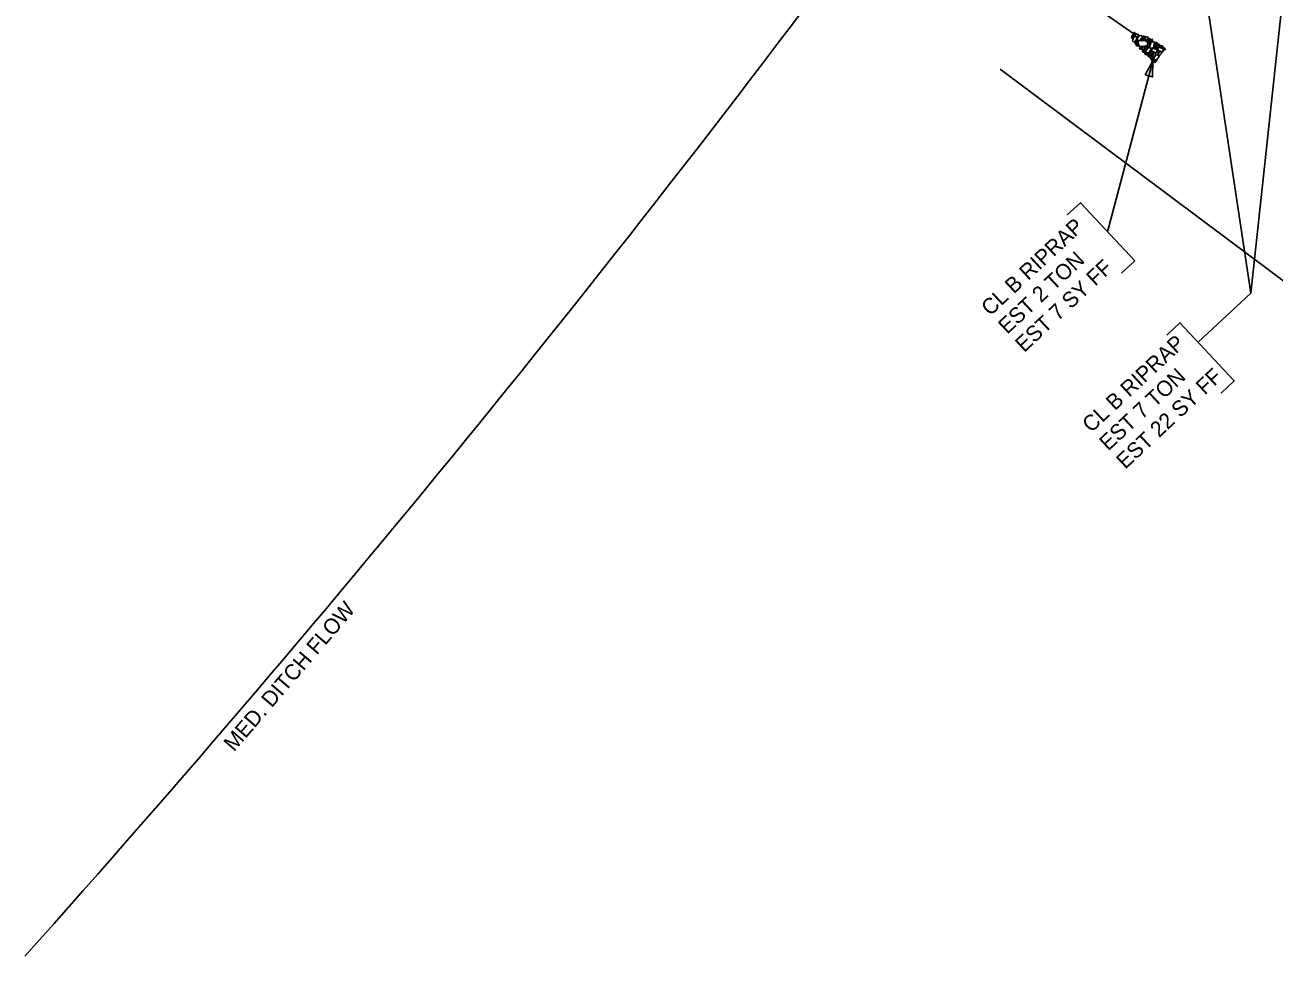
# Model space of a CAD drawing. Extents: x 2384780 to 2405432, y 547869 to 573706.
# Drawn here: x 2399231.9 to 2399632.8, y 560808.7 to 561107.7 of the extents above; entities that cross this region are included whole.
import ezdxf

# ---------------------------------------------------------------- set-up
doc = ezdxf.new("R2010")
doc.units = 0
for name, color, linetype in [('Old_Level_1', 7, 'Continuous'), ('Old_Level_19', 7, 'Continuous'), ('Old_Level_20', 7, 'Continuous'), ('Old_Level_41', 7, 'Continuous'), ('Old_Level_5', 7, 'Continuous')]:
    doc.layers.add(name, color=color, linetype=linetype)

msp = doc.modelspace()

# ---------------------------------------------------------------- linework, layer by layer
at = {"layer": 'Old_Level_1'}
msp.add_line((2399588.2, 561104.64), (2399559.77, 561124.39), dxfattribs=at)
at = {"layer": 'Old_Level_19'}
msp.add_arc((2395689.31, 563976), 4752, 318.20137, 323.62463, dxfattribs=at)
at = {"layer": 'Old_Level_20'}
msp.add_line((2399593.9, 561096.19), (2399579.38, 561041.29), dxfattribs=at)
for points in [[(2399587.72, 561104.23), (2399587.66, 561104.01), (2399587.58, 561103.47), (2399587.23, 561103.47), (2399587.08, 561103.58), (2399587.18, 561104.24), (2399587.48, 561104.4), (2399587.72, 561104.23)], [(2399587.42, 561102.46), (2399587.5, 561102.89), (2399587.79, 561103.88), (2399588.48, 561104.05), (2399588.9, 561103.71), (2399588.48, 561102.56), (2399587.92, 561102.25), (2399587.52, 561102.38)], [(2399588.18, 561105.14), (2399588.12, 561104.91), (2399588.02, 561104.34), (2399587.69, 561104.39), (2399587.52, 561104.49), (2399587.64, 561105.09), (2399587.93, 561105.3), (2399588.18, 561105.14)], [(2399589.32, 561103.96), (2399588.97, 561103.98), (2399588.35, 561104.12), (2399588.2, 561104.64), (2399588.42, 561104.98), (2399589.27, 561104.64), (2399589.41, 561104.31), (2399589.32, 561103.96)], [(2399589.1, 561101.53), (2399588.83, 561101.44), (2399588.36, 561101.62), (2399588.3, 561101.93), (2399588.41, 561102.09), (2399589.02, 561101.93), (2399589.15, 561101.72), (2399589.1, 561101.53)], [(2399588.36, 561102.23), (2399588.48, 561102.42), (2399588.72, 561102.8), (2399589.04, 561102.73), (2399589.2, 561102.62), (2399588.86, 561102.12), (2399588.52, 561102), (2399588.36, 561102.23)], [(2399588.85, 561102.98), (2399589.03, 561103.45), (2399589.59, 561104.3), (2399590.35, 561104.21), (2399590.58, 561103.82), (2399589.83, 561102.83), (2399589.26, 561102.73), (2399588.85, 561102.98)], [(2399592.25, 561101.18), (2399591.45, 561100.87), (2399589.71, 561100.8), (2399589.09, 561101.84), (2399589.34, 561102.63), (2399591.49, 561102.77), (2399592.24, 561102.13), (2399592.41, 561101.2)], [(2399590.83, 561102.73), (2399590.56, 561102.65), (2399590.09, 561102.84), (2399590.01, 561103.14), (2399590.15, 561103.27), (2399590.73, 561103.12), (2399590.84, 561102.95), (2399590.83, 561102.73)], [(2399591.34, 561103.03), (2399591.03, 561102.98), (2399590.59, 561103.19), (2399590.5, 561103.47), (2399590.63, 561103.65), (2399591.27, 561103.45), (2399591.36, 561103.25), (2399591.34, 561103.03)], [(2399591.56, 561103.58), (2399591.28, 561103.49), (2399590.81, 561103.67), (2399590.74, 561103.98), (2399590.88, 561104.12), (2399591.45, 561103.96), (2399591.57, 561103.8), (2399591.56, 561103.58)], [(2399591.38, 561103.04), (2399591.5, 561103.44), (2399591.83, 561103.94), (2399592.39, 561103.84), (2399592.56, 561103.54), (2399592.01, 561102.87), (2399591.61, 561102.87), (2399591.38, 561103.04)], [(2399593.09, 561101.98), (2399592.82, 561101.92), (2399592.38, 561102.12), (2399592.3, 561102.41), (2399592.42, 561102.6), (2399593.02, 561102.4), (2399593.11, 561102.2), (2399593.09, 561101.98)], [(2399593.28, 561102.78), (2399593, 561102.7), (2399592.53, 561102.89), (2399592.46, 561103.18), (2399592.6, 561103.31), (2399593.17, 561103.17), (2399593.29, 561103), (2399593.28, 561102.78)], [(2399594.44, 561102.11), (2399594.4, 561101.57), (2399594.17, 561100.41), (2399593.23, 561100.27), (2399592.82, 561100.54), (2399593.26, 561101.96), (2399593.89, 561102.38), (2399594.5, 561102.22)], [(2399593.8, 561103.04), (2399593.85, 561102.78), (2399593.71, 561102.37), (2399593.39, 561102.23), (2399593.11, 561102.41), (2399593.38, 561102.95), (2399593.64, 561103.14), (2399593.8, 561103.04)], [(2399595.4, 561101.62), (2399595.12, 561101.53), (2399594.66, 561101.71), (2399594.58, 561102.01), (2399594.71, 561102.15), (2399595.29, 561102.01), (2399595.4, 561101.85), (2399595.4, 561101.62)], [(2399589.46, 561100.9), (2399589.16, 561100.86), (2399588.69, 561101.04), (2399588.61, 561101.32), (2399588.74, 561101.51), (2399589.37, 561101.31), (2399589.47, 561101.12), (2399589.46, 561100.9)], [(2399589.64, 561100.06), (2399589.74, 561100.36), (2399589.97, 561100.79), (2399590.31, 561100.68), (2399590.49, 561100.48), (2399590.08, 561100), (2399589.78, 561099.93), (2399589.64, 561100.06)], [(2399590.42, 561099.67), (2399590.4, 561100.03), (2399590.61, 561100.71), (2399591.05, 561100.82), (2399591.29, 561100.64), (2399591.09, 561099.79), (2399590.72, 561099.58), (2399590.42, 561099.67)], [(2399591.45, 561098.95), (2399591.18, 561098.86), (2399590.71, 561099.04), (2399590.65, 561099.35), (2399590.76, 561099.51), (2399591.38, 561099.37), (2399591.5, 561099.15), (2399591.45, 561098.95)], [(2399591.77, 561100.13), (2399591.74, 561099.89), (2399591.64, 561099.37), (2399591.26, 561099.39), (2399591.12, 561099.48), (2399591.27, 561100.11), (2399591.46, 561100.21), (2399591.77, 561100.13)], [(2399592.18, 561100.28), (2399591.92, 561100.19), (2399591.46, 561100.4), (2399591.38, 561100.68), (2399591.5, 561100.86), (2399592.11, 561100.7), (2399592.23, 561100.48), (2399592.18, 561100.28)], [(2399592.19, 561098.21), (2399591.91, 561098.12), (2399591.44, 561098.3), (2399591.39, 561098.61), (2399591.49, 561098.77), (2399592.11, 561098.63), (2399592.23, 561098.41), (2399592.19, 561098.21)], [(2399591.57, 561099.07), (2399591.77, 561099.56), (2399592.41, 561100.35), (2399593.08, 561100.26), (2399593.42, 561099.83), (2399592.67, 561098.89), (2399591.97, 561098.73), (2399591.57, 561099.07)], [(2399592.2, 561100.88), (2399592.27, 561101.2), (2399592.59, 561101.48), (2399592.98, 561101.45), (2399593.07, 561101.25), (2399592.74, 561100.75), (2399592.36, 561100.77), (2399592.2, 561100.88)], [(2399592.94, 561098.77), (2399592.88, 561098.55), (2399592.69, 561098.08), (2399592.39, 561098.02), (2399592.26, 561098.1), (2399592.34, 561098.63), (2399592.61, 561098.81), (2399592.83, 561098.8)], [(2399593.31, 561097.42), (2399592.98, 561097.41), (2399592.5, 561097.56), (2399592.47, 561097.86), (2399592.57, 561098), (2399593.21, 561097.86), (2399593.33, 561097.64), (2399593.31, 561097.42)], [(2399593.74, 561097.99), (2399593.55, 561098.04), (2399593.02, 561098.14), (2399593, 561098.53), (2399593.11, 561098.68), (2399593.77, 561098.51), (2399593.78, 561098.24), (2399593.74, 561097.99)], [(2399593.88, 561098.75), (2399593.57, 561098.68), (2399593.1, 561098.87), (2399593.04, 561099.18), (2399593.17, 561099.32), (2399593.75, 561099.16), (2399593.89, 561098.97), (2399593.88, 561098.75)], [(2399593.73, 561100.21), (2399594.17, 561100.14), (2399595.18, 561099.82), (2399595.31, 561099.15), (2399595.02, 561098.72), (2399593.88, 561099.16), (2399593.46, 561099.62), (2399593.7, 561100.1)], [(2399594.85, 561098.65), (2399594.82, 561098.27), (2399594.52, 561097.6), (2399594.1, 561097.53), (2399593.86, 561097.7), (2399594.13, 561098.5), (2399594.42, 561098.75), (2399594.85, 561098.65)], [(2399594.15, 561096.78), (2399594.37, 561097.25), (2399594.88, 561098.08), (2399595.67, 561097.98), (2399595.94, 561097.53), (2399595.22, 561096.57), (2399594.59, 561096.49), (2399594.15, 561096.78)], [(2399595.13, 561100.18), (2399594.89, 561100.12), (2399594.35, 561100.28), (2399594.29, 561100.6), (2399594.43, 561100.73), (2399595.05, 561100.59), (2399595.16, 561100.43), (2399595.13, 561100.18)], [(2399594.5, 561100.88), (2399594.57, 561101.19), (2399594.89, 561101.48), (2399595.28, 561101.45), (2399595.37, 561101.25), (2399595.04, 561100.75), (2399594.65, 561100.77), (2399594.5, 561100.88)], [(2399596.05, 561098.93), (2399595.77, 561098.85), (2399595.29, 561099.02), (2399595.24, 561099.33), (2399595.34, 561099.48), (2399595.97, 561099.34), (2399596.1, 561099.12), (2399596.05, 561098.93)], [(2399596.08, 561101.53), (2399596.12, 561101.18), (2399595.94, 561100.78), (2399595.64, 561100.65), (2399595.38, 561100.81), (2399595.65, 561101.35), (2399595.88, 561101.56), (2399596.08, 561101.53)], [(2399595.68, 561100.39), (2399596.19, 561100.42), (2399597.18, 561100.13), (2399597.35, 561099.43), (2399596.95, 561099.06), (2399595.79, 561099.46), (2399595.52, 561099.88), (2399595.62, 561100.43)], [(2399595.57, 561098.19), (2399595.71, 561098.53), (2399596.07, 561099.06), (2399596.62, 561098.93), (2399596.81, 561098.7), (2399596.2, 561097.99), (2399595.82, 561097.96), (2399595.57, 561098.19)], [(2399596.24, 561100.46), (2399596.32, 561100.77), (2399596.63, 561101.05), (2399597.02, 561101.01), (2399597.11, 561100.81), (2399596.77, 561100.31), (2399596.39, 561100.35), (2399596.24, 561100.46)], [(2399597.94, 561099.87), (2399597.66, 561099.77), (2399597.2, 561099.96), (2399597.12, 561100.27), (2399597.26, 561100.4), (2399597.83, 561100.26), (2399597.95, 561100.09), (2399597.94, 561099.87)], [(2399593.14, 561096.86), (2399593.23, 561097.17), (2399593.46, 561097.59), (2399593.8, 561097.49), (2399593.98, 561097.29), (2399593.57, 561096.8), (2399593.27, 561096.74), (2399593.14, 561096.86)], [(2399593.46, 561096.26), (2399593.56, 561096.55), (2399593.8, 561096.98), (2399594.14, 561096.88), (2399594.32, 561096.68), (2399593.9, 561096.19), (2399593.6, 561096.13), (2399593.46, 561096.26)], [(2399594.37, 561095.82), (2399594.47, 561096.11), (2399594.71, 561096.54), (2399595.05, 561096.44), (2399595.23, 561096.24), (2399594.82, 561095.75), (2399594.51, 561095.69), (2399594.37, 561095.82)], [(2399566.45, 561046.7), (2399570.67, 561050.63), (2399588.1, 561031.94), (2399583.88, 561028.01)], [(2399598.41, 561008.14), (2399602.62, 561012.07), (2399620.05, 560993.38), (2399615.84, 560989.44)]]:
    msp.add_lwpolyline(points, dxfattribs=at)
msp.add_lwpolyline([(2399591.42, 561091.68), (2399593.9, 561096.19), (2399593.83, 561091.04)], close=True, dxfattribs=at)
at = {"layer": 'Old_Level_41'}
for p in [(2399641.94, 561174.31), (2399610.72, 561118.74), (2399608.47, 561005.8)]:
    msp.add_line(p, (2399625.41, 561021.59), dxfattribs=at)
at = {"layer": 'Old_Level_5'}
msp.add_line((2399544.89, 561093.47), (2399723.29, 560960.09), dxfattribs=at)

# ---------------------------------------------------------------- texts
at = {"layer": 'Old_Level_1'}
for s, p in [('CL B RIPRAP', (2399574.14, 560976.56)), ('EST 22 SY FF', (2399585.06, 560964.86)), ('EST 7 TON', (2399579.6, 560970.71))]:
    msp.add_text(s, height=5, rotation=43, dxfattribs=at).set_placement(p)
at = {"layer": 'Old_Level_19'}
msp.add_text('MED. DITCH FLOW', height=5, rotation=49.4179, dxfattribs=at).set_placement((2399299, 560874.12))
at = {"layer": 'Old_Level_20'}
for s, p in [('CL B RIPRAP', (2399541.7, 561014.04)), ('EST 2 TON', (2399547.16, 561008.18)), ('EST 7 SY FF', (2399552.61, 561002.33))]:
    msp.add_text(s, height=5, rotation=43, dxfattribs=at).set_placement(p)

doc.saveas('drawing.dxf')
